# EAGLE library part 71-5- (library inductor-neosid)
TRANSFORMER adjustable filter transformer with tap
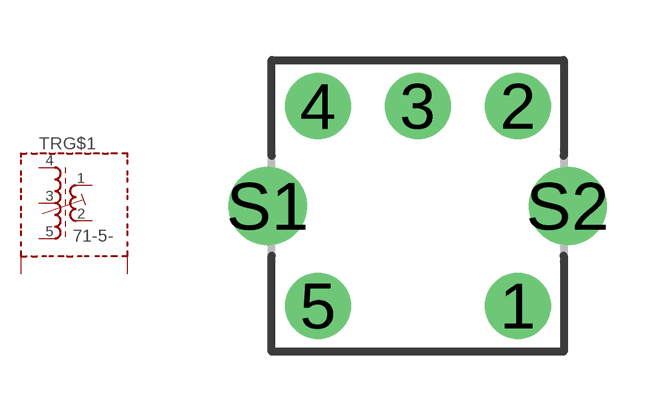
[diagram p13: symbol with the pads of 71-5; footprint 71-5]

Designator prefix TR; gates G$1=SMF51-4 G$2=SHIELD3

## 71-5-45123 (OC_FARNELL: unknown; OC_NEWARK: unknown)  [71-5]
1  G$1:A2  pas
2  G$1:E2  pas
3  G$1:Z  pas
4  G$1:A1  pas
5  G$1:E1  pas
S1  G$2:S1  pas
S2  G$2:S2  pas

## 71-5-42153 (OC_FARNELL: unknown; OC_NEWARK: unknown)  [71-5]
1  G$1:A2  pas
2  G$1:E1  pas
3  G$1:Z  pas
4  G$1:A1  pas
5  G$1:E2  pas
S1  G$2:S1  pas
S2  G$2:S2  pas

## 71-5-13542 (OC_FARNELL: unknown; OC_NEWARK: unknown)  [71-5]
1  G$1:A1  pas
2  G$1:Z  pas
3  G$1:E1  pas
4  G$1:E2  pas
5  G$1:A2  pas
S1  G$2:S1  pas
S2  G$2:S2  pas

## 71-5-43512 (OC_FARNELL: unknown; OC_NEWARK: unknown)  [71-5]
1  G$1:E2  pas
2  G$1:Z  pas
3  G$1:E1  pas
4  G$1:A1  pas
5  G$1:A2  pas
S1  G$2:S1  pas
S2  G$2:S2  pas

## 71-5-51423 (OC_FARNELL: unknown; OC_NEWARK: unknown)  [71-5]
1  G$1:E1  pas
2  G$1:E2  pas
3  G$1:Z  pas
4  G$1:A2  pas
5  G$1:A1  pas
S1  G$2:S1  pas
S2  G$2:S2  pas

## 71-5-32154 (OC_FARNELL: unknown; OC_NEWARK: unknown)  [71-5]
1  G$1:A2  pas
2  G$1:E1  pas
3  G$1:A1  pas
4  G$1:Z  pas
5  G$1:E2  pas
S1  G$2:S1  pas
S2  G$2:S2  pas

## 71-5-15423 (OC_FARNELL: unknown; OC_NEWARK: unknown)  [71-5]
1  G$1:A1  pas
2  G$1:E2  pas
3  G$1:Z  pas
4  G$1:A2  pas
5  G$1:E1  pas
S1  G$2:S1  pas
S2  G$2:S2  pas

## 71-5-24153 (OC_FARNELL: unknown; OC_NEWARK: unknown)  [71-5]
1  G$1:A2  pas
2  G$1:A1  pas
3  G$1:Z  pas
4  G$1:E1  pas
5  G$1:E2  pas
S1  G$2:S1  pas
S2  G$2:S2  pas

## 71-5-24513 (OC_FARNELL: unknown; OC_NEWARK: unknown)  [71-5]
1  G$1:E2  pas
2  G$1:A1  pas
3  G$1:Z  pas
4  G$1:E1  pas
5  G$1:A2  pas
S1  G$2:S1  pas
S2  G$2:S2  pas

## 71-5-42513 (OC_FARNELL: unknown; OC_NEWARK: unknown)  [71-5]
1  G$1:E2  pas
2  G$1:E1  pas
3  G$1:Z  pas
4  G$1:A1  pas
5  G$1:A2  pas
S1  G$2:S1  pas
S2  G$2:S2  pas

## 71-5-34153 (OC_FARNELL: unknown; OC_NEWARK: unknown)  [71-5]
1  G$1:A2  pas
2  G$1:Z  pas
3  G$1:A1  pas
4  G$1:E1  pas
5  G$1:E2  pas
S1  G$2:S1  pas
S2  G$2:S2  pas

## 71-5-34512 (OC_FARNELL: unknown; OC_NEWARK: unknown)  [71-5]
1  G$1:E2  pas
2  G$1:Z  pas
3  G$1:A1  pas
4  G$1:E1  pas
5  G$1:A2  pas
S1  G$2:S1  pas
S2  G$2:S2  pas

## 71-5-41325 (OC_FARNELL: unknown; OC_NEWARK: unknown)  [71-5]
1  G$1:E1  pas
2  G$1:E2  pas
3  G$1:A2  pas
4  G$1:A1  pas
5  G$1:Z  pas
S1  G$2:S1  pas
S2  G$2:S2  pas

## 71-5-34152 (OC_FARNELL: unknown; OC_NEWARK: unknown)  [71-5]
Pads as for 71-5

## Footprint 71-5 (pad centres in mm)
RF COIL ASSEMBLY 1 winding, 5 pads, grid 2.5 mm
drill 1.1 round: 1 2.5,-2.5; 2 2.5,2.5; 3 0,2.5; 4 -2.5,2.5; 5 -2.5,-2.5
drill 1.3 round: S1 -3.75,0; S2 3.75,0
